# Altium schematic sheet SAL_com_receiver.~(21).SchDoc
size A4
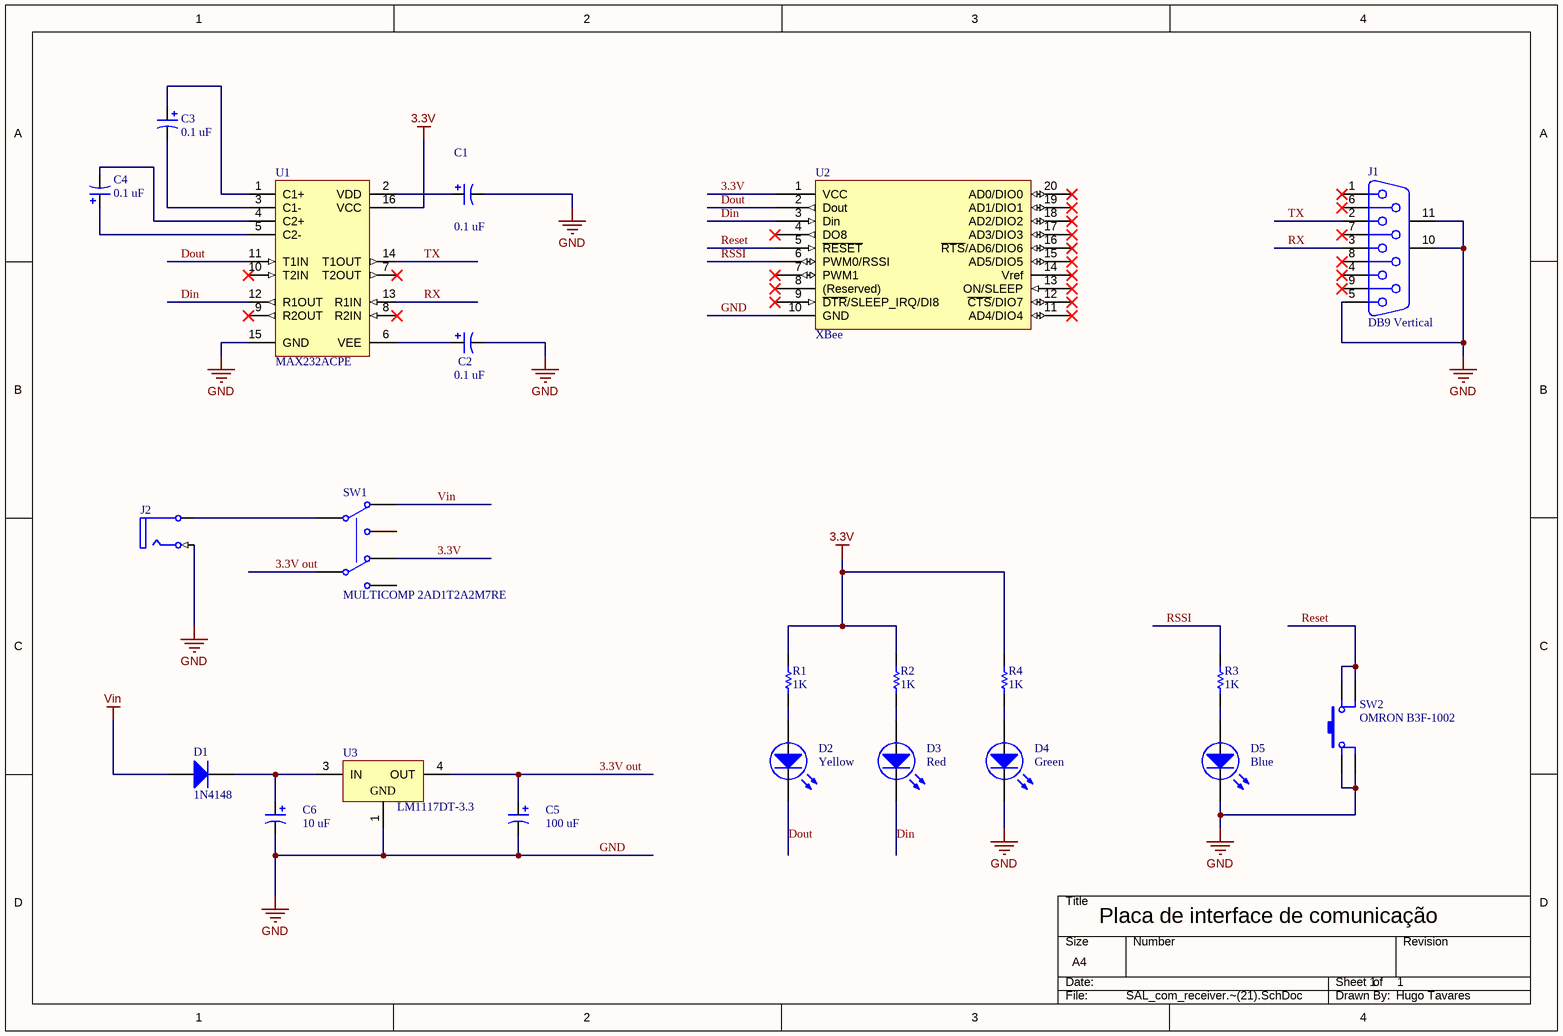
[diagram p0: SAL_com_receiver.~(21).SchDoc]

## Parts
C1  0.1 uF  [KEMET C410C104M5U5CA-TR]
C2  0.1 uF  [KEMET C410C104M5U5CA-TR]
C3  0.1 uF  [KEMET C410C104M5U5CA-TR]
C4  0.1 uF  [KEMET C410C104M5U5CA-TR]
C5  100 uF  [PANASONIC ECA1HAM101X]
C6  10 uF  [PANASONIC ECA1HAM100X]
D1  1N4148  [FAIRCHILD 1N4118]
D2  Yellow  [VISHAY TLLR4401]
D3  Red  [VISHAY TLLR4401]
D4  Green  [VISHAY TLLR4401]
D5  Blue  [VISHAY TLLR4401]
J1  DB9 Vertical  [TYCO 2-106505-2]
J2  RCA  [RCA/4.5-H2]  (value not drawn)
R1  1K  [Resistência]
R2  1K  [Resistência]
R3  1K  [Resistência]
R4  1K  [Resistência]
SW1  MULTICOMP 2AD1T2A2M7RE  [MULTICOMP 2AD1T2A2M7RE]
SW2  OMRON B3F-1002  [OMRON B3F-1002]
U1  MAX232ACPE  [PE16A]
U2  XBee  [XBee]
U3  LM1117DT-3.3  [TD03B_N]

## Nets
3.3V: R1.1 R2.1 R4.1 SW1.3(NC1) U1.16(VCC) U2.1(VCC)
GND: C1.2 C2.2 C5.1 C6.1 D4.2(K) D5.2(K) J1.5 J1.10(MH1) J1.11(MH2) J2.2B(Signal) SW1.GND SW2.3 SW2.4 U1.15(GND) U2.10(GND) U3.1(GND)
Vin: D1.A SW1.6(NC2)
3.3V out: C5.2 SW1.2(COMMON1) U3.4(OUT)
Din: D3.2(K) U1.12(R1OUT) U2.3(Din)
Dout: D2.2(K) U1.11(T1IN) U2.2(Dout)
Reset: SW2.1 SW2.2 U2.5(~{RESET})
RSSI: R3.1 U2.6(PWM0/RSSI)
RX: J1.3 U1.13(R1IN)
TX: J1.2 U1.14(T1OUT)
NetC1_1: C1.1 U1.2(VDD)
NetC2_1: C2.1 U1.6(VEE)
NetC3_1: C3.1 U1.1(C1+)
NetC3_2: C3.2 U1.3(C1-)
NetC4_1: C4.1 U1.5(C2-)
NetC4_2: C4.2 U1.4(C2+)
NetC6_2: C6.2 D1.K U3.3(IN)
NetD2_1: D2.1(A) R1.2
NetD3_1: D3.1(A) R2.2
NetD4_1: D4.1(A) R4.2
NetD5_1: D5.1(A) R3.2
NetJ2_1A: J2.1A(Ground) SW1.5(COMMON2)

Not connected (* = marked no-connect by the designer): J1 1* 4* 6* 7* 8* 9*; SW1 1(NO1) 4(NO2); U1 7(T2OUT)* 8(R2IN)* 9(R2OUT)* 10(T2IN)*; U2 4(DO8)* 7(PWM1)* 8((Reserved))* 9(~{DTR}/SLEEP_IRQ/DI8)* 11(AD4/DIO4)* 12(~{CTS}/DIO7)* 13(ON/SLEEP)* 14(Vref)* 15(AD5/DIO5)* 16(~{RTS}/AD6/DIO6)* 17(AD3/DIO3)* 18(AD2/DIO2)* 19(AD1/DIO1)* 20(AD0/DIO0)*

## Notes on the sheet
- Placa de interface de comunicação
- 1      1
- Hugo Tavares

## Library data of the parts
C1-C4 = KEMET C410C104M5U5CA-TR: 0.1 uF axial capacitor 50V Z5U
C5 = PANASONIC ECA1HAM101X
C6 = PANASONIC ECA1HAM100X
D1 = FAIRCHILD 1N4148: Diode Switching 75V 500 MW DO-35
D2-D5 = VISHAY TLLG4401: Green LED PCB 3mm
J1 = TYCO 2-106505-2
J2 = RCA: RCA Phono Jack, Right Angle, Thru-Hole, Snap-In; PCB_Layout: Complies with manufacturer's recommendation.; DrillAndSlotSize: Corresponds to nominal value.
R1-R4 = Resistência
SW2 = OMRON B3F-1002: 6.0mm Tact Switch
U1 = MAX232ACPE: +5V Powered, Multi-Channel RS-232 Driver/Receiver
U3 = LM1117DT-3.3: 800mA Low-Dropout Linear Regulator; Manufacturer: National Semiconductor; CompType: LDO IC; PackageTopMarking: NSUZXYTT*LM1117*DT-3.3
